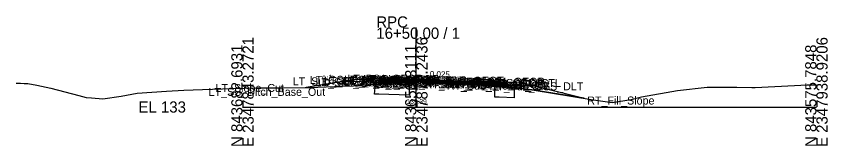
# Model space of a CAD drawing. Extents: x -26 to 203, y -10 to 7538.
# Drawn here: x 0 to 202.8, y 2990.3 to 3022.7 of the extents above; entities that cross this region are included whole.
import ezdxf

# ---------------------------------------------------------------- set-up
doc = ezdxf.new("R2010")
doc.units = 0
for name, color, linetype in [('Default', 7, 'Continuous'), ('Exist CMT Pavement', 7, 'Continuous'), ('Exist Cross Section Cell', 7, 'Continuous'), ('Exist XS Center Line Elevation Label', 7, 'Continuous'), ('Exist XS Ground Line', 7, 'Continuous'), ('Prop CMT Pvmt Course 1', 7, 'Continuous'), ('Prop CMT Pvmt Course 1 Wedge', 7, 'Continuous'), ('Prop CMT Pvmt Course 2', 7, 'Continuous'), ('Prop CMT Pvmt Course 2 Wedge', 7, 'Continuous'), ('Prop CMT Pvmt Course 3', 7, 'Continuous'), ('Prop CMT Pvmt Course 3 Wedge', 7, 'Continuous'), ('Prop CMT Pvmt Surface', 7, 'Continuous'), ('Prop CMT Pvmt Surface Shoulder', 7, 'Continuous'), ('Prop CMT Pvmt Wedge Surface 1', 7, 'Continuous'), ('Prop CMT Pvmt Wedge Surface 2', 7, 'Continuous'), ('Prop CMT Pvmt Wedge Surface 3', 7, 'Continuous'), ('Prop CMT Shld Paved Course 1', 7, 'Continuous'), ('Prop CMT Shld Paved Course 2', 7, 'Continuous'), ('Prop CMT Shld Paved Course 3', 7, 'Continuous'), ('Prop CMT Slope Grass', 7, 'Continuous'), ('Prop CMT Subgrade Earthwork', 7, 'Continuous'), ('Prop Road Sect_ Recs - UC (Outline)', 7, 'Continuous'), ('Prop XS Earthwork Shape', 7, 'Continuous'), ('Prop XS SE Text', 7, 'Continuous'), ('Prop XS Side Slope Text', 7, 'Continuous'), ('Scratch_Level_0', 7, 'Continuous')]:
    doc.layers.add(name, color=color, linetype=linetype)

msp = doc.modelspace()

# ---------------------------------------------------------------- linework, layer by layer
at = {"layer": 'Exist CMT Pavement'}
msp.add_line((100, 3006.39), (101.67, 3006.35), dxfattribs=at)
at = {"layer": 'Exist Cross Section Cell'}
for p, q in [((100, 3000), (100, 3019.86)), ((56.55, 3000), (100, 3000)), ((100, 3000), (200, 3000))]:
    msp.add_line(p, q, dxfattribs=at)
at = {"layer": 'Exist XS Ground Line'}
msp.add_lwpolyline([(0, 3005.99), (1.03, 3005.95), (1.99, 3005.9), (2.89, 3005.85), (5.19, 3005.44), (8.63, 3004.73), (15.63, 3002.85), (17.51, 3002.37), (18.81, 3002.28), (21.66, 3002.03), (26.21, 3002.71), (30.25, 3003.45), (37.54, 3003.92), (41.85, 3004.19), (46.56, 3004.4), (51.57, 3004.57), (59.98, 3004.76), (66.57, 3004.78), (73.4, 3004.87), (81.56, 3005.18), (84.34, 3005.29), (89.43, 3005.68), (98.2, 3006.32), (98.68, 3006.33), (100.22, 3006.4), (100.92, 3006.38), (101.66, 3006.35), (102.45, 3006.31), (102.87, 3006.28), (103.72, 3006.24), (104.72, 3006.19), (105.51, 3006.15), (106.19, 3006.11), (108.49, 3005.98), (109.05, 3005.95), (109.54, 3005.92), (112.23, 3005.75), (112.59, 3005.72), (112.91, 3005.7), (114.35, 3005.61), (116.35, 3005.49), (117.74, 3005.42), (119.6, 3005.26), (121.46, 3005.13), (126.4, 3004.6), (129.45, 3004.19), (143.74, 3001.9), (148.97, 3001.11), (152.15, 3001.6), (153.66, 3001.84), (156.29, 3002.51), (165.25, 3004.13), (172.71, 3004.95), (180.1, 3004.92), (183.86, 3004.89), (184.66, 3004.86), (194.54, 3005.35), (197.65, 3005.51), (200, 3005.57)], dxfattribs=at)
at = {"layer": 'Prop CMT Pvmt Course 1'}
for p, q in [((100, 3006.87), (96, 3006.97)), ((96, 3006.97), (96, 3006.72)), ((96, 3006.72), (100, 3006.62)), ((100, 3006.62), (100, 3006.87)), ((100, 3006.87), (112, 3006.57)), ((100, 3006.62), (100, 3006.87)), ((100, 3006.62), (100, 3006.74)), ((100, 3006.74), (100, 3006.74)), ((100, 3006.74), (100, 3006.62)), ((101.67, 3006.7), (100, 3006.74)), ((100, 3006.74), (100, 3006.62)), ((100, 3006.62), (100, 3006.62)), ((100, 3006.62), (100, 3006.62)), ((101.67, 3006.57), (101.67, 3006.7)), ((112, 3006.32), (101.67, 3006.57)), ((112, 3006.57), (112, 3006.32))]:
    msp.add_line(p, q, dxfattribs=at)
at = {"layer": 'Prop CMT Pvmt Course 1 Wedge'}
msp.add_line((100, 3006.74), (101.67, 3006.7), dxfattribs=at)
at = {"layer": 'Prop CMT Pvmt Course 2'}
for p, q in [((100, 3006.62), (96, 3006.72)), ((96, 3006.72), (96, 3006.38)), ((96, 3006.38), (100, 3006.28)), ((100, 3006.28), (100, 3006.62)), ((101.67, 3006.24), (101.67, 3006.57)), ((101.67, 3006.57), (112, 3006.32)), ((112, 3005.98), (101.67, 3006.24)), ((112, 3006.32), (112, 3005.98))]:
    msp.add_line(p, q, dxfattribs=at)
at = {"layer": 'Prop CMT Pvmt Course 2 Wedge'}
msp.add_line((100, 3006.62), (101.67, 3006.57), dxfattribs=at)
at = {"layer": 'Prop CMT Pvmt Course 3'}
for p, q in [((100, 3006.28), (96, 3006.38)), ((96, 3006.38), (96, 3006.05)), ((100, 3005.95), (100, 3006.28)), ((101.67, 3006.24), (112, 3005.98)), ((101.67, 3005.91), (101.67, 3006.24)), ((96, 3006.05), (100, 3005.95)), ((112, 3005.65), (101.67, 3005.91)), ((112, 3005.98), (112, 3005.65))]:
    msp.add_line(p, q, dxfattribs=at)
at = {"layer": 'Prop CMT Pvmt Course 3 Wedge'}
msp.add_line((100, 3006.28), (101.67, 3006.24), dxfattribs=at)
at = {"layer": 'Prop CMT Pvmt Surface'}
for q in [(96, 3006.97), (112, 3006.57)]:
    msp.add_line((100, 3006.87), q, dxfattribs=at)
at = {"layer": 'Prop CMT Pvmt Surface Shoulder'}
for p, q in [((96, 3006.97), (92, 3007.07)), ((112, 3006.57), (122, 3006.32))]:
    msp.add_line(p, q, dxfattribs=at)
at = {"layer": 'Prop CMT Pvmt Wedge Surface 1'}
for p, q in [((100, 3006.74), (101.67, 3006.7)), ((101.67, 3006.7), (101.67, 3006.57)), ((101.67, 3006.57), (112, 3006.32)), ((112, 3006.32), (112, 3006.57))]:
    msp.add_line(p, q, dxfattribs=at)
at = {"layer": 'Prop CMT Pvmt Wedge Surface 2'}
for p, q in [((100, 3006.62), (112, 3006.32)), ((112, 3006.32), (112, 3006.57))]:
    msp.add_line(p, q, dxfattribs=at)
at = {"layer": 'Prop CMT Pvmt Wedge Surface 3'}
for p, q in [((100, 3006.28), (112, 3005.98)), ((112, 3005.98), (112, 3006.57))]:
    msp.add_line(p, q, dxfattribs=at)
at = {"layer": 'Prop CMT Shld Paved Course 1'}
for p, q in [((92, 3007.07), (91.76, 3006.82)), ((91.76, 3006.82), (96, 3006.72)), ((96, 3006.97), (92, 3007.07)), ((96, 3006.72), (96, 3006.97)), ((112, 3006.57), (122, 3006.32)), ((112, 3006.32), (112, 3006.57)), ((122.26, 3006.06), (112, 3006.32)), ((122, 3006.32), (122.26, 3006.06))]:
    msp.add_line(p, q, dxfattribs=at)
at = {"layer": 'Prop CMT Shld Paved Course 2'}
for p, q in [((91.76, 3006.82), (91.43, 3006.5)), ((91.43, 3006.5), (96, 3006.38)), ((96, 3006.72), (91.76, 3006.82)), ((96, 3006.38), (96, 3006.72)), ((112, 3006.32), (122.26, 3006.06)), ((112, 3005.98), (112, 3006.32)), ((122.6, 3005.72), (112, 3005.98)), ((122.26, 3006.06), (122.6, 3005.72))]:
    msp.add_line(p, q, dxfattribs=at)
at = {"layer": 'Prop CMT Shld Paved Course 3'}
for p, q in [((90.93, 3006.51), (90.61, 3006.18)), ((90.61, 3006.18), (96, 3006.05)), ((91.43, 3006.5), (90.93, 3006.51)), ((96, 3006.38), (91.43, 3006.5)), ((96, 3006.05), (96, 3006.38)), ((112, 3005.98), (122.6, 3005.72)), ((112, 3005.65), (112, 3005.98)), ((123.44, 3005.36), (112, 3005.65)), ((122.6, 3005.72), (123.1, 3005.7)), ((123.1, 3005.7), (123.44, 3005.36))]:
    msp.add_line(p, q, dxfattribs=at)
at = {"layer": 'Prop CMT Slope Grass'}
for p, q in [((84, 3006.79), (72.43, 3004.86)), ((92, 3007.07), (84, 3006.79)), ((122, 3006.32), (126, 3006.18)), ((126, 3006.18), (141.92, 3002.2))]:
    msp.add_line(p, q, dxfattribs=at)
at = {"layer": 'Prop CMT Subgrade Earthwork'}
for p, q in [((90.61, 3006.18), (81.72, 3006.41)), ((96, 3006.05), (90.61, 3006.18)), ((100, 3005.95), (100, 3006.39)), ((101.67, 3005.91), (101.67, 3006.35)), ((100, 3005.95), (96, 3006.05)), ((101.67, 3005.91), (112, 3005.65)), ((112, 3005.65), (123.44, 3005.36)), ((123.44, 3005.36), (129.9, 3005.2))]:
    msp.add_line(p, q, dxfattribs=at)
at = {"layer": 'Prop Road Sect_ Recs - UC (Outline)'}
for points in [[(98.22, 3005.99), (98.22, 3002.99), (90.61, 3003.18), (89.58, 3003.21), (89.76, 3005.71), (94.87, 3006.08)], [(124.43, 3004.81), (124.44, 3002.33), (120.71, 3002.44), (119.64, 3002.46), (119.64, 3005.26), (121.46, 3005.13)]]:
    msp.add_lwpolyline(points, close=True, dxfattribs=at)
at = {"layer": 'Prop XS Earthwork Shape'}
for points in [[(81.72, 3006.41), (72.43, 3004.86), (73.4, 3004.87), (81.56, 3005.18), (84.34, 3005.29), (89.43, 3005.68), (94.87, 3006.08), (90.61, 3006.18)], [(100, 3005.95), (100, 3006.39), (98.68, 3006.33), (98.2, 3006.32), (94.87, 3006.08), (96, 3006.05)], [(100, 3006.39), (100.22, 3006.4), (100.92, 3006.38), (101.67, 3006.35)], [(114.35, 3005.61), (114.82, 3005.58), (112, 3005.65), (101.67, 3005.91), (101.67, 3006.35), (102.45, 3006.31), (102.87, 3006.28), (103.72, 3006.24), (104.72, 3006.19), (105.51, 3006.15), (106.19, 3006.11), (108.49, 3005.98), (109.05, 3005.95), (109.54, 3005.92), (112.23, 3005.75), (112.59, 3005.72), (112.91, 3005.7)], [(123.44, 3005.36), (129.9, 3005.2), (141.92, 3002.2), (129.45, 3004.19), (126.4, 3004.6), (121.46, 3005.13), (119.6, 3005.26), (117.74, 3005.42), (116.35, 3005.49), (114.82, 3005.58)]]:
    msp.add_lwpolyline(points, close=True, dxfattribs=at)

# ---------------------------------------------------------------- texts
at = {"layer": 'Default'}
msp.add_text('-', height=0.0001, dxfattribs=at).set_placement((56.55, 3000))
at = {"layer": 'Exist Cross Section Cell'}
for s, p in [('RPC', (90, 3019.86)), ('16+50.00 / 1', (90, 3017.06)), ('EL 133', (30.55, 2998.6))]:
    msp.add_text(s, height=2.8, dxfattribs=at).set_placement(p)
for s, p in [('E 2347843.2721', (59.35, 2990)), ('E 2347872.2436', (102.8, 2990)), ('E 2347938.9206', (202.8, 2990)), ('N 843682.6931', (56.55, 2990)), ('N 843650.3111', (100, 2990)), ('N 843575.7848', (200, 2990))]:
    msp.add_text(s, height=2.8, rotation=90, dxfattribs=at).set_placement(p)
at = {"layer": 'Exist XS Center Line Elevation Label'}
msp.add_text('139.39', height=1.2, dxfattribs=at).set_placement((97.55, 3000.79))
at = {"layer": 'Prop XS SE Text'}
msp.add_text('0.025', height=1.5, rotation=358.5679, dxfattribs=at).set_placement((103.34, 3007.53))
at = {"layer": 'Prop XS Side Slope Text'}
for s, rotation, p in [('6:1', 9.4623, (76.54, 3006.27)), ('4:1', 345.9638, (130.66, 3005.68))]:
    msp.add_text(s, height=1.5, rotation=rotation, dxfattribs=at).set_placement(p)
at = {"layer": 'Scratch_Level_0'}
for s, p in [('LT_Sub_OSS_DLT', (69.12, 3005.41)), ('LT_GS_OS_CTL', (73.37, 3005.79)), ('LT_Sub_Trench_Out', (74.81, 3005.18)), ('LT_PS3_Shelf_Out', (76.92, 3005.51)), ('LT_PS3_OEOP', (81.67, 3005.5)), ('LT_PS2_OEOP', (81.99, 3005.82)), ('LT_PS1_OEOP', (82.8, 3006.07)), ('LT_Sub_OEOT', (86.08, 3005.05)), ('LT_PV2_OEOT', (86.17, 3005.72)), ('LT_PV3_OEOT', (86.17, 3005.38)), ('RT_PV_Sub_Tie_Out', (86.56, 3005.35)), ('LT_PV1_OEOT', (86.74, 3005.97)), ('RT_PV_IEEOP_EG', (88.14, 3005.39)), ('RT_PV_OEEOP_EG', (89.16, 3005.35)), ('LT_Sub_OEEOP', (89.21, 3004.95)), ('LT_PV2_OEEOP', (89.31, 3005.62)), ('LT_PV3_OEEOP', (89.31, 3005.28)), ('LT_PV1_OEEOP', (89.87, 3005.74)), ('RT_PV2_IEEOP', (89.91, 3005.62)), ('RT_PV3_IEEOP', (89.91, 3005.28)), ('LT_PV2_IEEOP', (89.95, 3005.62)), ('RT_PV1_IEEOP', (90.47, 3005.74)), ('LT_PV1_IEEOP', (90.52, 3005.74)), ('RT_Sub_OEEOP', (90.83, 3004.91)), ('RT_PV2_OEEOP', (90.93, 3005.57)), ('RT_PV3_OEEOP', (90.93, 3005.24)), ('RT_PV1_OEEOP', (91.49, 3005.7)), ('PV2_PGL', (93.91, 3005.62)), ('PV1_PGL', (94.47, 3005.87)), ('RT_Sub_OEOT', (102.03, 3004.65)), ('RT_PV2_OEOT', (102.13, 3005.32)), ('RT_PV3_OEOT', (102.13, 3004.98)), ('RT_PV1_OEOT', (102.69, 3005.57)), ('RT_Sub_Trench_Out', (107.6, 3004.36)), ('RT_PS3_Shelf_Out', (109.04, 3004.7)), ('RT_PS2_OEOP', (112.45, 3005.06)), ('RT_PS1_OEOP', (112.76, 3005.32)), ('RT_PS3_OEOP', (112.79, 3004.72)), ('RT_GS_OS_CTL', (115.32, 3005)), ('RT_Sub_OSS_DLT', (118.27, 3004.18)), ('LT_SS_Ditch_Base_Out', (48.08, 3002.79)), ('LT_Slope_Cut', (49.82, 3003.76)), ('RT_Fill_Slope', (142.73, 3000.62))]:
    msp.add_text(s, height=2, dxfattribs=at).set_placement(p)

doc.saveas('drawing.dxf')
